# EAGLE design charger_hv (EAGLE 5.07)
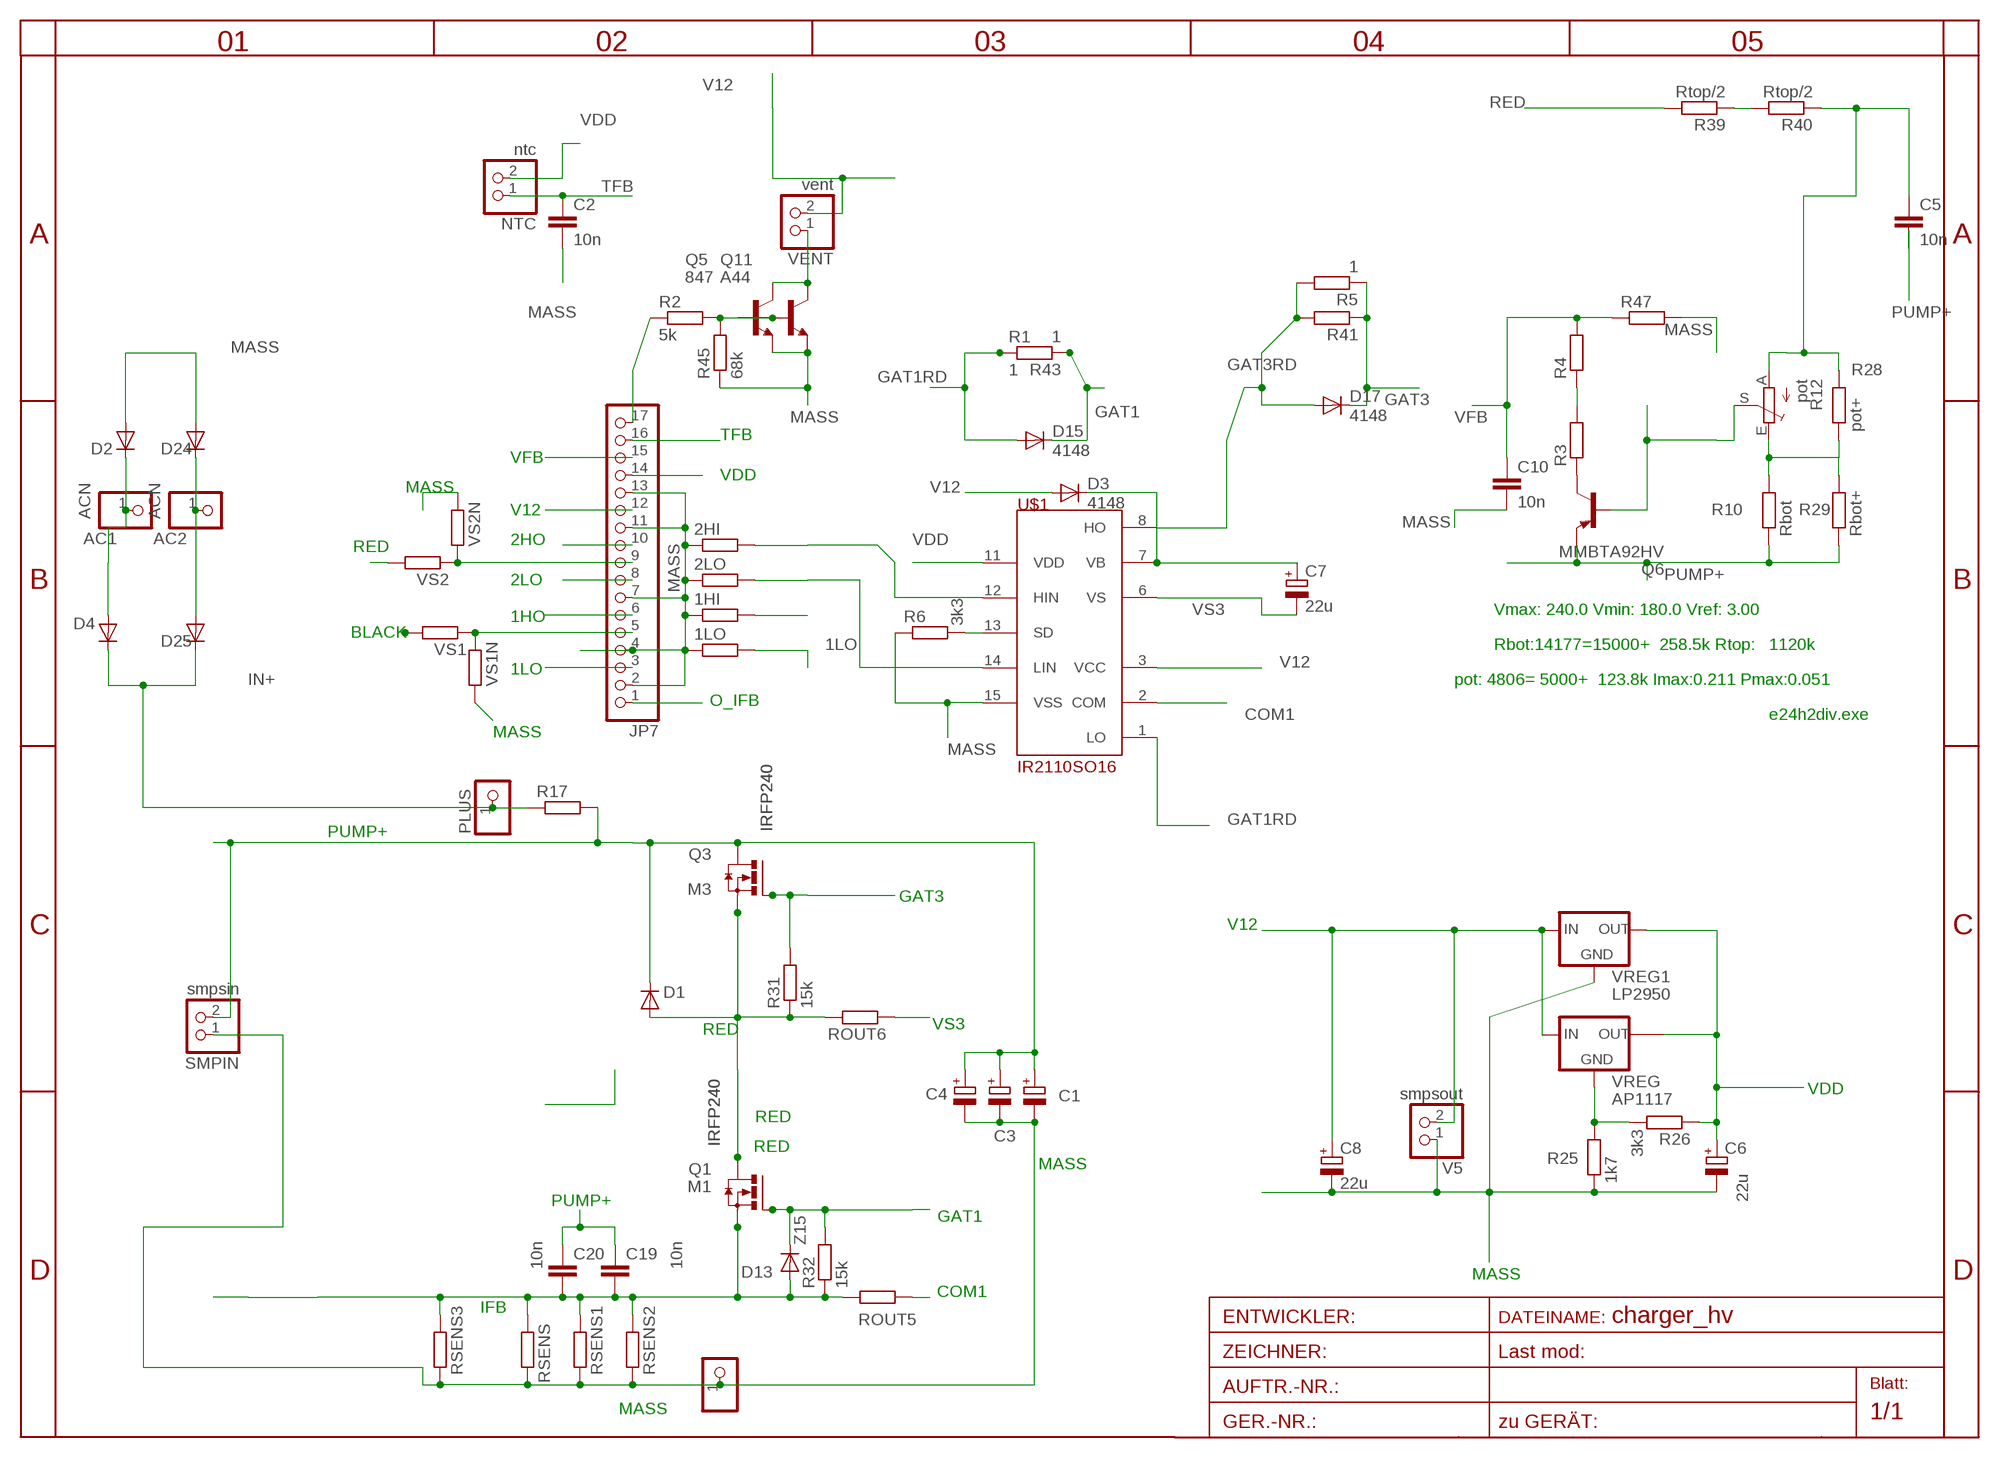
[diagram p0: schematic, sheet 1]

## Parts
1HI  R-EU_R0805  [R0805]
1LO  R-EU_R0805  [R0805]
2HI  R-EU_R0805  [R0805]
2LO  R-EU_R0805  [R0805]
AC1  ACN  PINHD-1X12MM3  [1X2MM3]
AC2  ACN  PINHD-1X12MM3  [1X2MM3]
C1  CPOL-EUE5-13  [E5-13]
C2  10n  C-EUC0805  [C0805]
C3  CPOL-EUE5-13  [E5-13]
C4  CPOL-EUE5-13  [E5-13]
C5  10n  C-EUC0805  [C0805]
C6  22u  CPOL-EUSMCA  [SMC_A]
C7  22u  CPOL-EUSMCA  [SMC_A]
C8  22u  CPOL-EUSMCA  [SMC_A]
C10  10n  C-EUC0805  [C0805]
C19  10n  C-EU050-024X044  [C050-024X044]
C20  10n  C-EU050-024X044  [C050-024X044]
D1  DIODE-TO220V  [TO220ACS]
D2  DIODE-TO220V  [TO220ACS]
D3  4148  DIODE-MINIMELF  [MINIMELF]
D4  DIODE-TO220V  [TO220ACS]
D13  Z15  DIODE-MINIMELF  [MINIMELF]
D15  4148  DIODE-MINIMELF  [MINIMELF]
D17  4148  DIODE-MINIMELF  [MINIMELF]
D24  DIODE-TO220V  [TO220ACS]
D25  DIODE-TO220V  [TO220ACS]
JP7  PINHD-1X17  [1X17]
M1  IRFP240  [TO247BV]
M3  IRFP240  [TO247BV]
MINUS  PINHD-1X12MM3  [1X2MM3]
NTC  ntc  PINHD-1X2STR  [1X02]
PLUS  PINHD-1X12MM3  [1X2MM3]
Q1  IRFP240  [TO247BV]
Q3  IRFP240  [TO247BV]
Q5  847  SMBTA45HV  [SOT23HV]
Q6  MMBTA92HV  [SOT23HV]
Q11  A44  -NPN-TO92-EBC  [TO92-EBC]
R1  1  R-EU_R2512  [R2512]
R2  5k  R-EU_R0603  [R0603]
R3  R-EU_R1206  [R1206]
R4  R-EU_R1206  [R1206]
R5  1  R-EU_R2512  [R2512]
R6  3k3  R-EU_R0805  [R0805]
R10  Rbot  R-EU_R0805  [R0805]
R12  pot  TRIM_EU-B64Y  [B64Y]
R17  R-EU_0309/10  [0309/10]
R25  1k7  R-EU_R0805  [R0805]
R26  3k3  R-EU_R0805  [R0805]
R28  pot+  R-EU_R0805  [R0805]
R29  Rbot+  R-EU_R0805  [R0805]
R31  15k  R-EU_R1206  [R1206]
R32  15k  R-EU_R1206  [R1206]
R39  Rtop/2  R-EU_R1206  [R1206]
R40  Rtop/2  R-EU_R1206  [R1206]
R41  1  R-EU_R1210  [R1210]
R43  1  R-EU_R1210  [R1210]
R45  68k  R-EU_R0805  [R0805]
R47  R-EU_R0805  [R0805]
ROUT5  R-EU_R2512  [R2512]
ROUT6  R-EU_R2512  [R2512]
RSENS  R-EU_WIRE  [WIRE]
RSENS1  R-EU_0309/10  [0309/10]
RSENS2  R-EU_0309/12  [0309/12]
RSENS3  R-EU_R2512  [R2512]
SMPIN  smpsin  PINHD-1X2STR  [1X02]
U$1  IR2110SO16  [SO16DW]
V5  smpsout  PINHD-1X2STR  [1X02]
VENT  vent  PINHD-1X2STR  [1X02]
VREG  AP1117  [SOT223]
VREG1  LP2950  LP2950TO92-2MIL  [TO92-2MIL]
VS1  R-EU_R1005  [R1005]
VS1N  R-EU_R0805  [R0805]
VS2  R-EU_R1005  [R1005]
VS2N  R-EU_R0805  [R0805]

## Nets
1HO: JP7.6
1LO: 1LO.2 JP7.3
2HO: 2HI.2 JP7.10 U$1.12(HIN)
2LO: 2LO.2 JP7.8 U$1.14(LIN)
BLACK: VS1.2
COM1: ROUT5.1 U$1.2(COM)
DFG: JP7.9 VS2.1 VS2N.2
GAT1: D13.C D15.C M1.G Q1.G R1.2 R32.2 R43.1
GAT1RD: D15.A R1.1 R43.2 U$1.1(LO)
GAT3: D17.C M3.G Q3.G R5.1 R31.2 R41.1
GAT3RD: D17.A R5.2 R41.2 U$1.8(HO)
GGG: AC1.1 D2.C D4.A
IFB: C19.2 C20.2 D13.A M1.S Q1.S R32.1 ROUT5.2 RSENS1.1 RSENS2.1 RSENS3.1 RSENS.1
IN+: D4.C D25.C PLUS.1 R17.1
JDH: JP7.5 VS1.1 VS1N.1
MASS: 1HI.1 1LO.1 2HI.1 2LO.1 C1.- C2.2 C3.- C4.- C6.- C8.- C10.2 D2.A D24.A JP7.2 JP7.4 JP7.7 JP7.11 JP7.13 MINUS.1 Q5.2(E) Q11.E R6.1 R25.1 R45.1 R47.2 RSENS1.2 RSENS2.2 RSENS3.2 RSENS.2 SMPIN.1 U$1.15(VSS) V5.1 VREG1.2(GND) VS1N.2 VS2N.1
N$1: Q5.3(C) Q11.C VENT.1
N$2: Q5.1(B) Q11.B R2.2 R45.2
N$3: JP7.17 R2.1
N$4: R6.2 U$1.13(SD)
N$5: Q6.3(C) R3.1
N$6: R3.2 R4.1
N$8: 1HI.2
N$15: R39.1 R40.2
N$17: R25.2 R26.2 VREG.1(GND)
N$19: C5.1 R12.A R28.2 R40.1
N$21: Q6.1(B) R12.S
N$22: AC2.1 D24.C D25.A
N$29: R10.2 R12.E R28.1 R29.2
O_IFB: JP7.1
PUMP+: C1.+ C3.+ C4.+ C5.2 C19.1 C20.1 D1.C M3.D Q3.D Q6.2(E) R10.1 R17.2 R29.1 SMPIN.2
RED: D1.A M1.D M3.S Q1.D Q3.S R31.1 R39.2 ROUT6.2 VS2.2
TFB: C2.1 JP7.16 NTC.1
V12: C8.+ D3.A JP7.12 U$1.3(VCC) V5.2 VENT.2 VREG1.3(IN) VREG.3(IN)
VB: C7.+ D3.C U$1.7(VB)
VDD: C6.+ JP7.14 NTC.2 R26.1 U$1.11(VDD) VREG1.1(OUT) VREG.4(TAB)
VFB: C10.1 JP7.15 R4.2 R47.1
VS3: C7.- ROUT6.1 U$1.6(VS)
Unconnected: VREG.2(OUT)

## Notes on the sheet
- Vmax: 240.0 Vmin: 180.0 Vref: 3.00
- Rbot:14177=15000+  258.5k Rtop:   1120k
- pot: 4806= 5000+  123.8k Imax:0.211 Pmax:0.051
- e24h2div.exe

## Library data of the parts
1HI 1LO 2HI 2LO R1-R5 R17 R31 R32 R45 R47 ROUT5 ROUT6 RSENS RSENS1-RSENS3 VS1 VS1N VS2 VS2N = rcl:R-EU_: RESISTOR, European symbol
AC1 AC2 MINUS PLUS = pinhead:PINHD-1X1: PIN HEADER
C1 C3 C4 C6-C8 = rcl:CPOL-EU: POLARIZED CAPACITOR, European symbol
C2 C5 C10 C19 C20 = rcl:C-EU: CAPACITOR, European symbol
D1-D4 D13 D15 D17 D24 D25 = diode:DIODE-: DIODE
JP7 = pinhead:PINHD-1X17: PIN HEADER
M1 M3 Q1 Q3 = transistor-power:IRFP240: HEXFET Power MosFet Source: http://www.irf.com/
NTC SMPIN V5 VENT = pinhead:PINHD-1X2: PIN HEADER
Q5 = transistor-npn:SMBTA45
Q6 = transistor-pnp:MMBTA92*: PNP Transistror
Q11 = transistor-neu-to92:*-NPN-: NPN Transistror
R6 R10 R25 R26 R28 R29 R39-R41 R43 = rcl-2:R-EU_: RESISTOR, European symbol
R12 = pot:TRIM_EU-: POTENTIOMETER
U$1 = ir2112:IR2110
VREG = v-reg:AP1117
VREG1 = v-reg:LP2950?*: Source: http://cache.national.com/ds/LP/LP2950.pdf

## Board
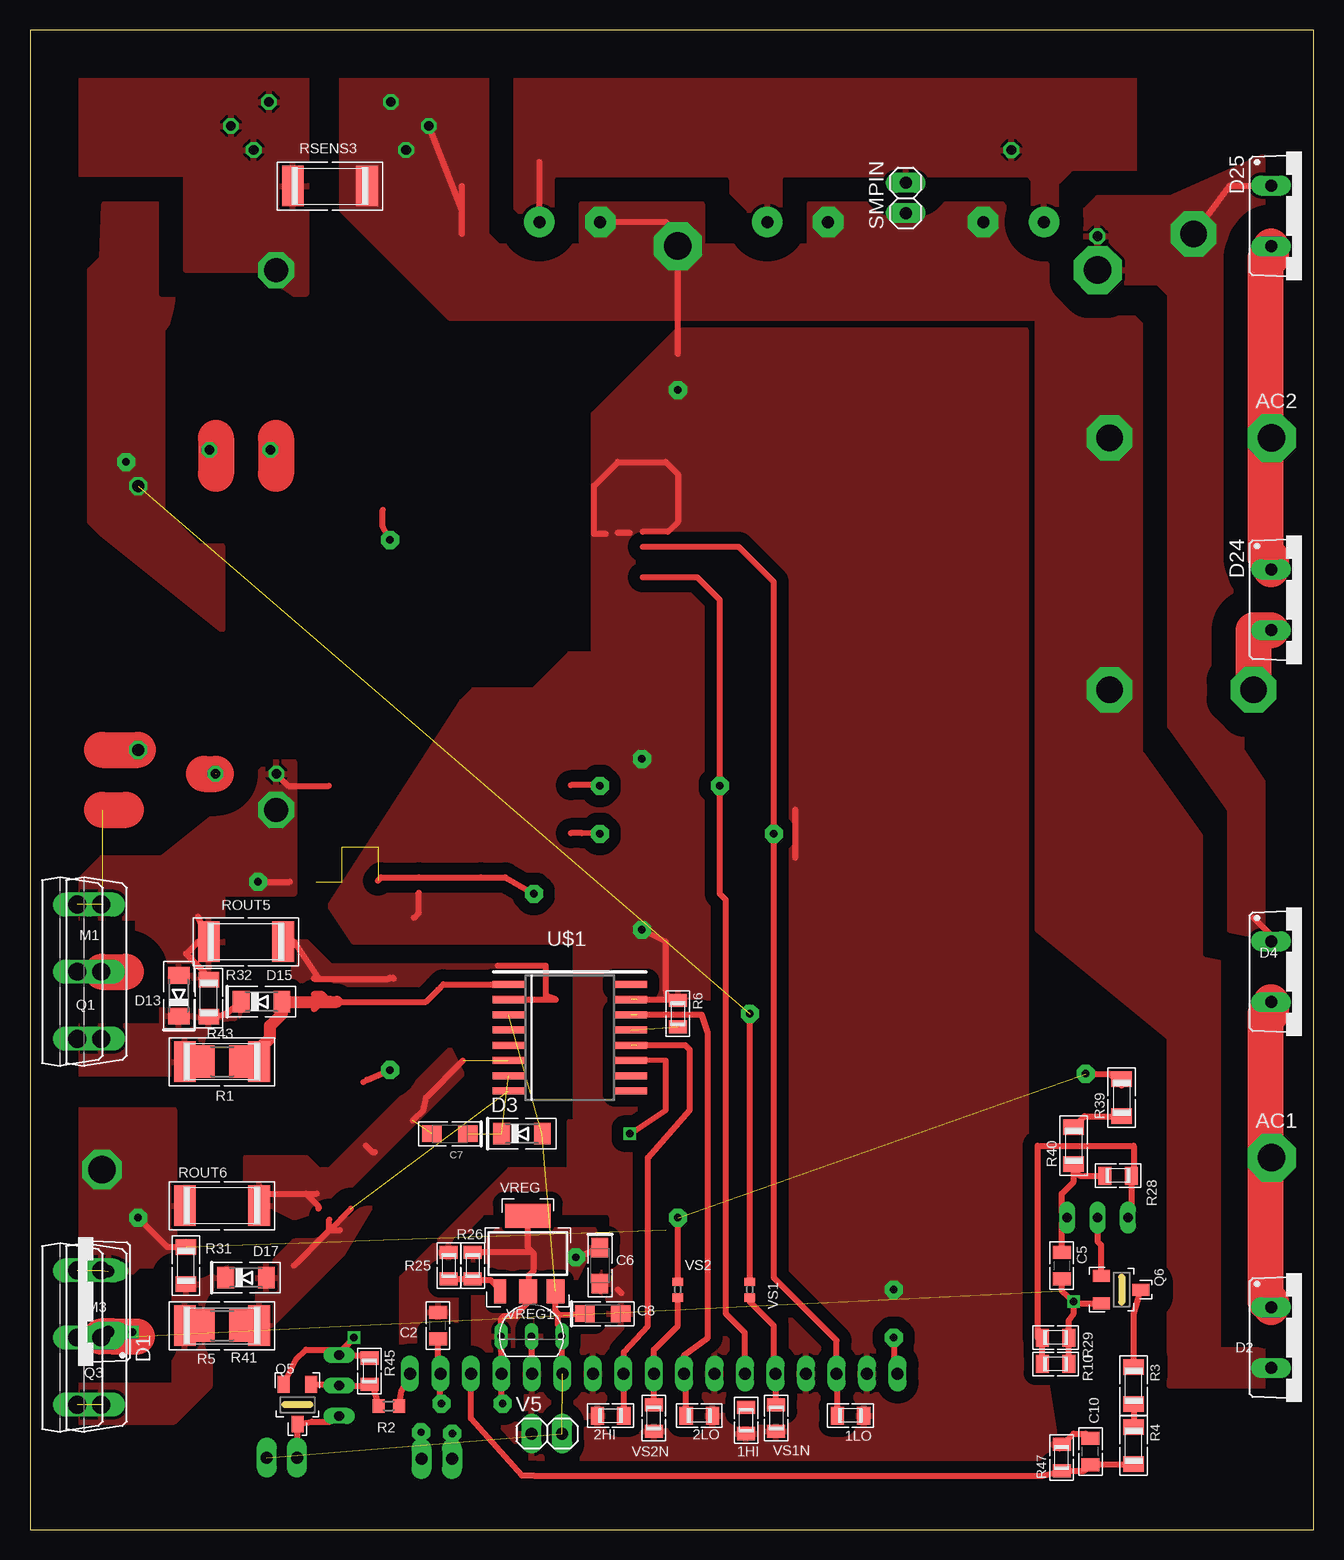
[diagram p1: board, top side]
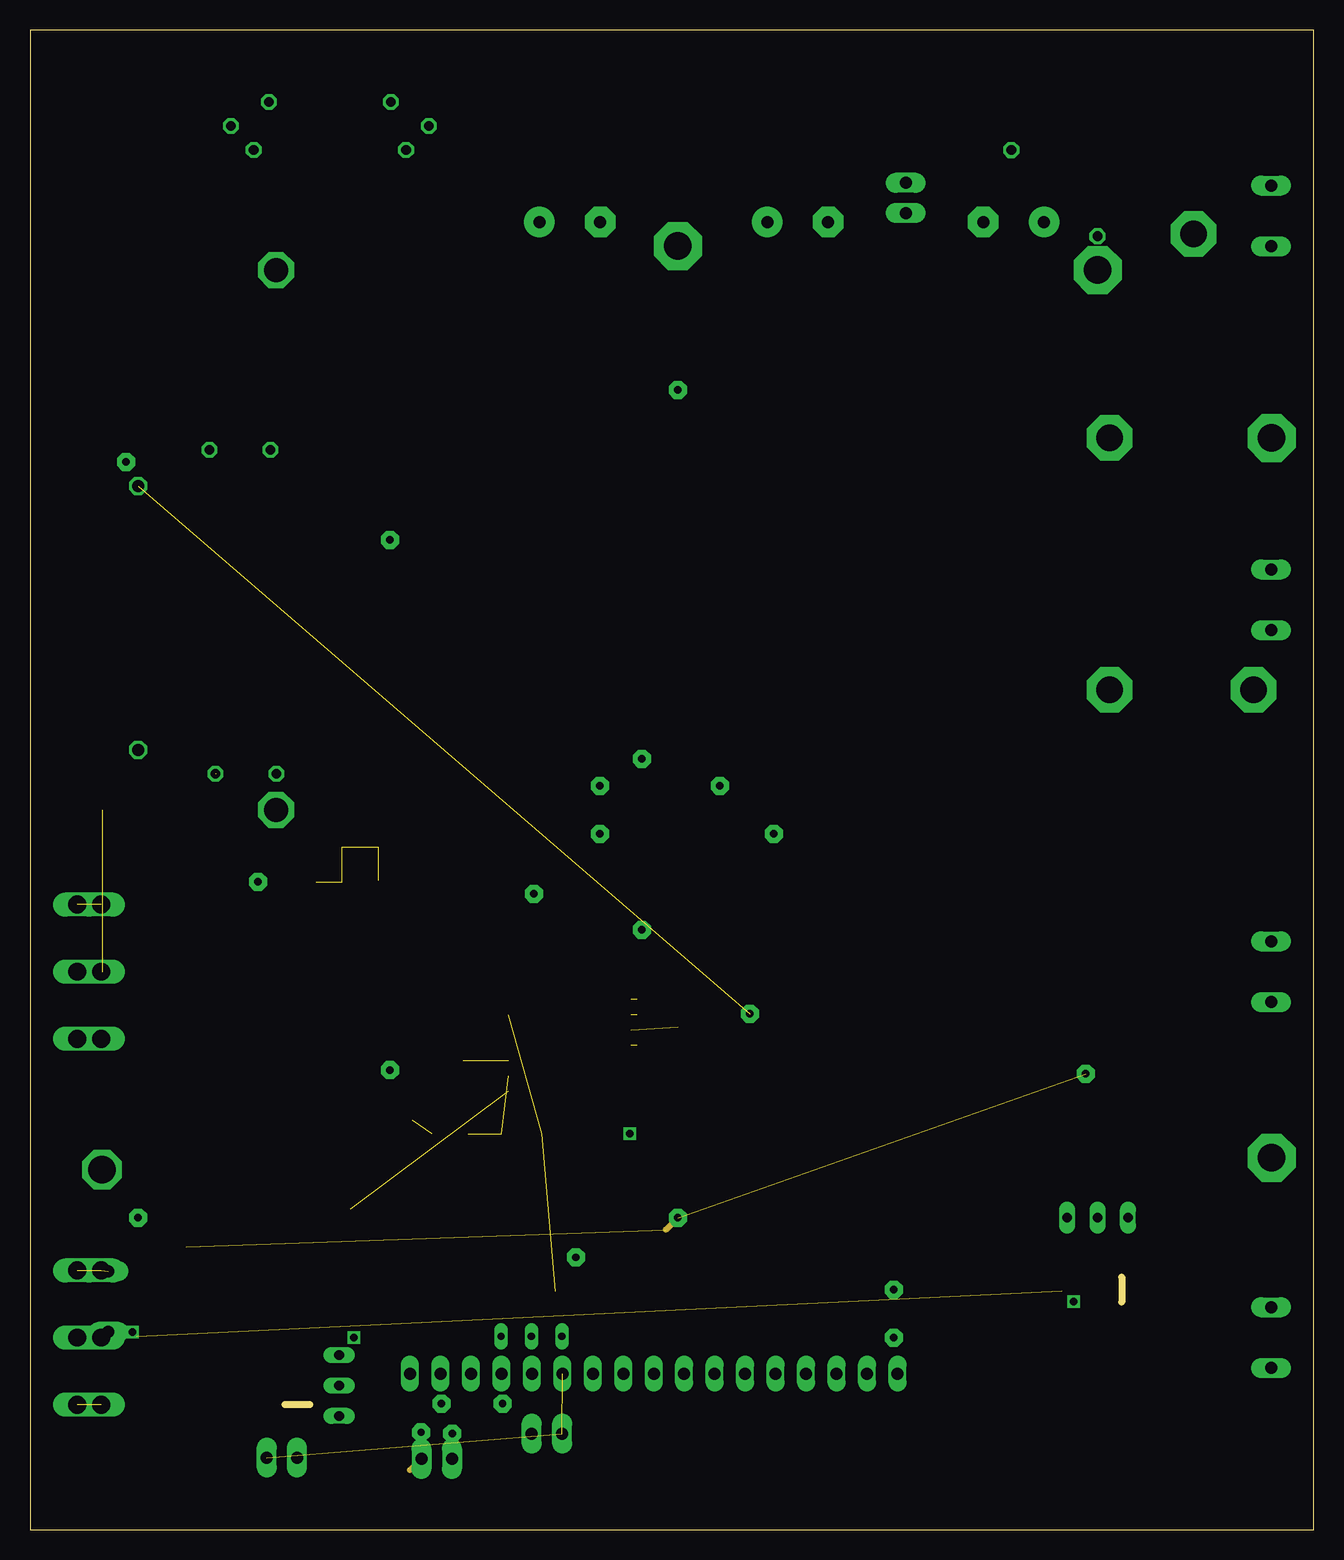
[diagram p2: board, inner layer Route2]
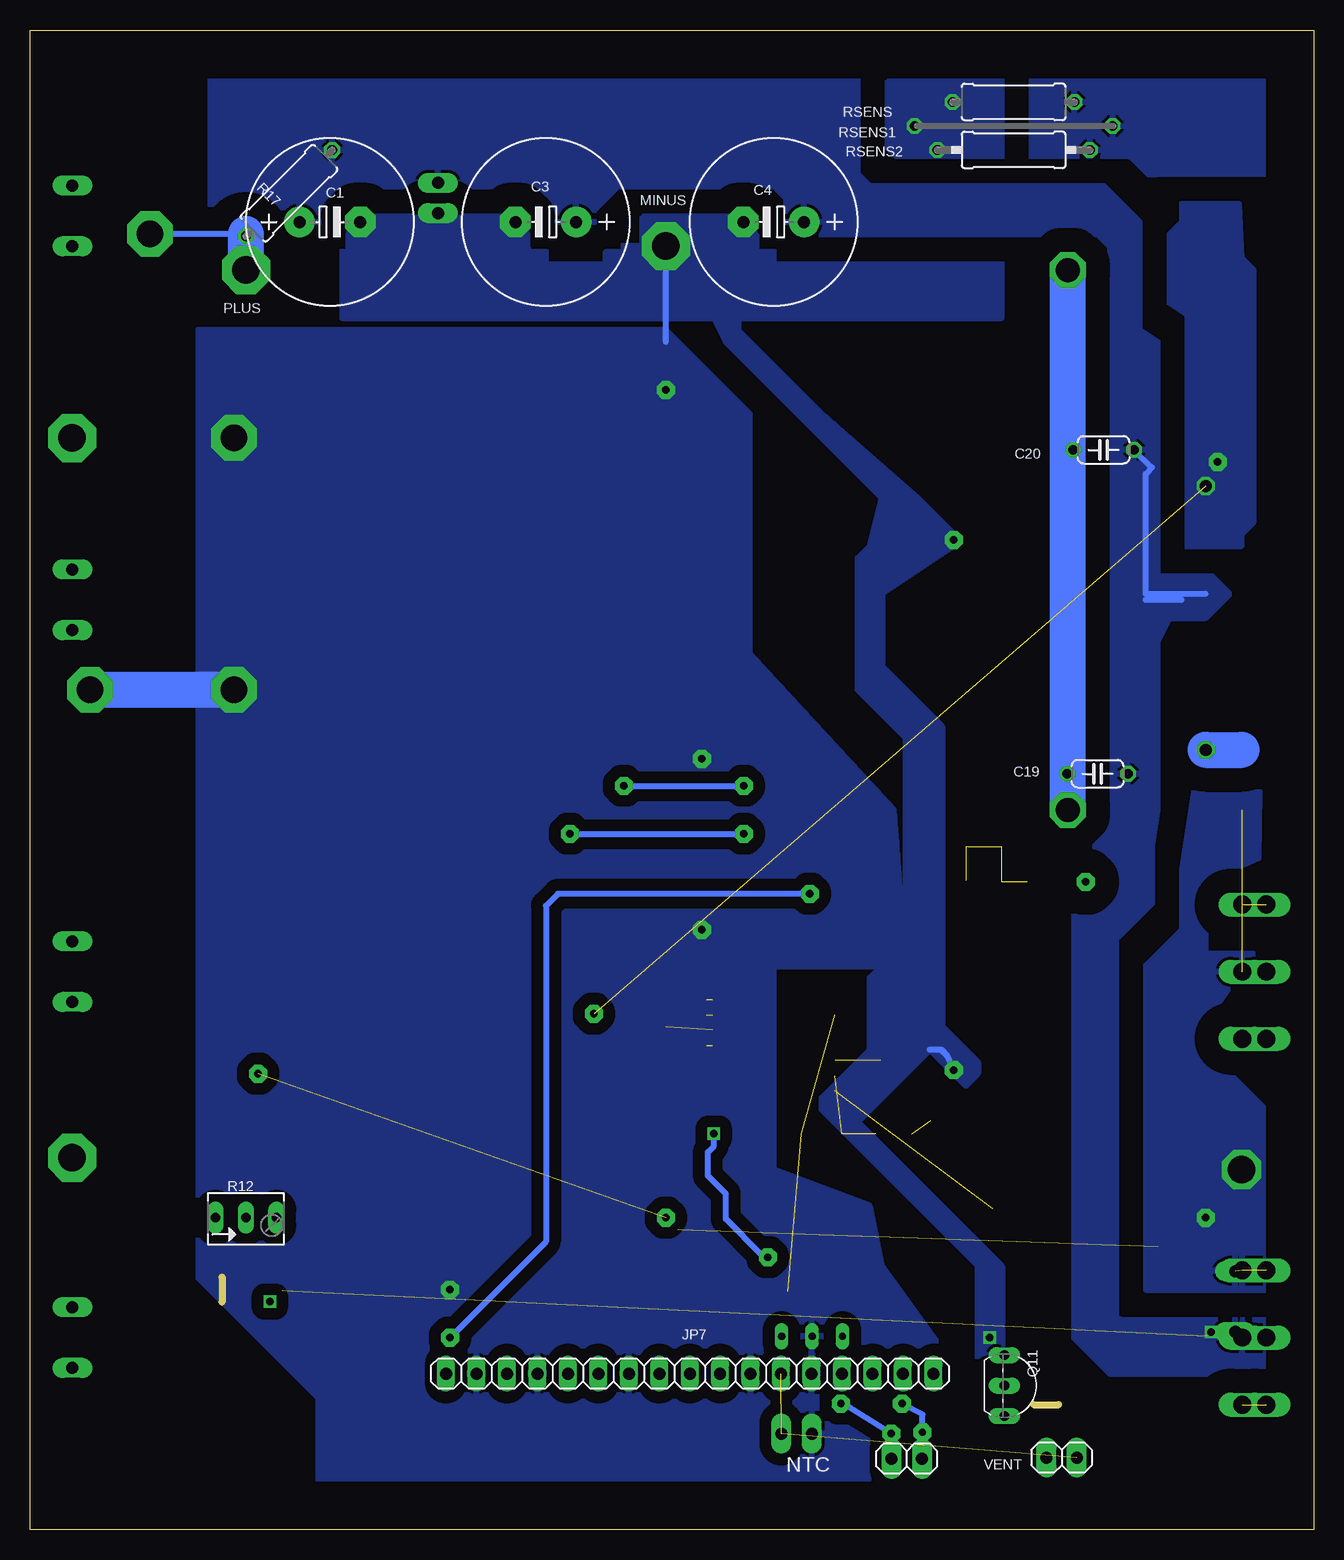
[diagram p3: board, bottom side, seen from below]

Size 107 x 125 mm. Coordinates in mm from the lower left corner, seen from the top.
Outline: 0,0 107,0 107,125 0,125 0,0
Copper layers (1*16): Top 0.035mm / dielectric 1.5mm / Bottom 0.035mm
Design rules "default *": minimum track width 10mil, minimum drill 20mil, track to track 8mil, track to pad 8mil, pad to pad 8mil, via to via 8mil, smd to smd 8mil, copper to edge 4mm, drill to drill 8mil, minimum pad ring 10mil, minimum via ring 8mil, stop-mask expansion 4mil, vias tented up to drill 0mil, thermal gap 10mil

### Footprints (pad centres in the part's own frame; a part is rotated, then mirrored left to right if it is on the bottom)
R0805 = smd 1.1 x 1.5: 1 -1.1,0; 2 1.1,0
1X2MM3 = drill 2.3 pad 4 octagon: 1 0,0
E5-13 = drill 1 pad 2.54 round: + -2.54,0 | drill 1 pad 2.54 octagon: - 2.54,0
C0805 = smd 1.1 x 1.5: 1 -1.1,0; 2 1.1,0
SMC_A = smd 1.6 x 1.4: + -1.5,0; - 1.5,0
C050-024X044 = drill 0.8 octagon: 1 -2.54,0; 2 2.54,0
TO220ACS = drill 1 pad 1.676 long: A 2.54,-2.54; C -2.54,-2.54
MINIMELF = smd 1.4 x 1.8: A 1.7,0; C -1.7,0
1X17 = drill 1 long: 1 -20.32,0; 2 -17.78,0; 3 -15.24,0; 4 -12.7,0; 5 -10.16,0; 6 -7.62,0; 7 -5.08,0; 8 -2.54,0; 9 0,0; 10 2.54,0; 11 5.08,0; 12 7.62,0; 13 10.16,0; 14 12.7,0; 15 15.24,0; 16 17.78,0; 17 20.32,0
TO247BV = drill 1.499 long: D 0,-2.921; G -5.588,-2.921; S 5.588,-2.921
1X02 = drill 1 pad 1.676 long: 1 -1.27,0; 2 1.27,0
SOT23HV = smd 1 x 1.4: 1 -1.15,-1.7; 2 1.15,-1.7; 3 0,1.6
TO92-EBC = drill 0.813 long: B 0,-1.27; C 2.54,-1.27; E -2.54,-1.27
R2512 = smd 1.8 x 3.4: 1 -3.1,0; 2 3.1,0
R0603 = smd 1 x 1.1: 1 -0.85,0; 2 0.85,0
R1206 = smd 1.3 x 1.7: 1 -1.55,0; 2 1.55,0
B64Y = drill 0.813 long: A 2.54,0; E -2.54,0; S 0,0
0309/10 = drill 0.813 octagon: 1 -5.08,0; 2 5.08,0
R1210 = smd 1.6 x 2.7: 1 -1.4,0; 2 1.4,0
WIRE = drill 0.813 octagon: 1 -8.25,0; 2 8.25,0
0309/12 = drill 0.813 octagon: 1 -6.35,0; 2 6.35,0
SO16DW = smd 0.6 x 2.7: 1 -4.445,-5.1; 2 -3.175,-5.1; 3 -1.905,-5.1; 4 -0.635,-5.1; 5 0.635,-5.1; 6 1.905,-5.1; 7 3.175,-5.1; 8 4.445,-5.1; 9 4.445,5.1; 10 3.175,5.1; 11 1.905,5.1; 12 0.635,5.1; 13 -0.635,5.1; 14 -1.905,5.1; 15 -3.175,5.1; 16 -4.445,5.1
SOT223 = smd 1 x 2: 1 -2.3,-3.15 | smd 1.5 x 2: 2 0,-3.15; 3 2.3,-3.15 | smd 3.8 x 2: 4 0,3.15
TO92-2MIL = drill 0.6 pad 0.813 long: 1 -2.54,0; 2 0,0; 3 2.54,0
R1005 = smd 0.7 x 0.9: 1 -0.65,0; 2 0.65,0

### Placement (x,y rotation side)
1HI  59.7,9.1 90 top
1LO  68.4,9.5 180 top
2HI  48.4,9.5 0 top
2LO  55.8,9.5 180 top
AC1  103.5,31 0 top
AC2  103.5,91 0 top
C1  82,109 0 bottom
C2  34,17 90 top
C3  64,109 180 bottom
C4  45,109 180 bottom
C5  86,22 270 top
C6  47.5,22 270 top
C7  35,33 180 top
C8  47.75,18 0 top
C10  88.4,6.5 90 top
C19  18,63 180 bottom
C20  17.5,90 180 bottom
D1  4,19 90 top
D2  106,16 270 top
D3  41,33 0 top
D4  106,46.5 270 top
D13  12.4,44.5 90 top
D15  19.3,44 0 top
D17  18,21 0 top
D24  106,77.5 270 top
D25  106,109.5 270 top
JP7  52,13 0 bottom
M1  3,46.5 90 top
M3  3,16 90 top
MINUS  54,107 270 bottom
NTC  33.9,5.9 180 bottom
PLUS  89,105 270 bottom
Q1  1,46.5 90 top
Q3  1,16 90 top
Q5  22.3,10.4 180 top
Q6  91,20 270 top
Q11  24.5,12 270 bottom
R1  16,39 180 top
R2  29.9,10.3 180 top
R3  92,12 270 top
R4  92,7 270 top
R5  16,17 0 top
R6  54,43 270 top
R10  85.5,13.8 180 top
R12  89,26 0 bottom
R17  85.4,111.4 45 bottom
R25  34.9,22 270 top
R26  36.9,22 270 top
R28  90.7,29.5 180 top
R29  85.5,16 180 top
R31  13,22 270 top
R32  14.9,44.3 270 top
R39  91,36 90 top
R40  87,32 90 top
R41  16,17 0 top
R43  16,39 0 top
R45  28.3,13.2 270 top
R47  86,6 90 top
ROUT5  18,49 180 top
ROUT6  16,27 180 top
RSENS  25,117 180 bottom
RSENS1  25,119 180 bottom
RSENS2  25,115 180 bottom
RSENS3  25,112 0 top
SMPIN  73,111 90 top
U$1  45,41 270 top
V5  43.1,8 0 top
VENT  21,6 0 bottom
VREG  41.5,23 0 top
VREG1  41.8,16.1 0 top
VS1  60,20 90 top
VS1N  62.2,9.3 270 top
VS2  54,20 90 top
VS2N  52,9.3 90 top

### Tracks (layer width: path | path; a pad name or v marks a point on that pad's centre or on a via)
1HO  (via drill 0.6 pad 1.5)
  Top 0.5: 45.1,62.05 46.95,62.05 v47.5,62 | 59.7,12.92 JP7.6 59.6,14.4 59.6,16.4 58,18 58,52.5 57.5,53 v57.5,62 57.5,73 57.5,77.5 56,79 55.63,79.36 51.1,79.36
  Bottom 0.5: v57.5,62 v47.5,62
1LO  (via drill 0.6 pad 1.5)
  Top 0.5: 45.1,58.05 46,58.05 v47.5,58 | 1LO.2 67.3,12.94 JP7.3 67.24,15.76 62,21 v62,58 62,79 59.09,81.91 51.1,81.91
  Bottom 0.5: v62,58 v47.5,58
2HO  (1 unrouted)
  Top 0.5: 2HI.2 49.5,12.96 JP7.10 49.5,14.8 51.5,17 51.5,21 51.5,22 51.5,31 55,35 55,40 54.63,40.37 50.6,40.37
2LO  (1 unrouted)
  Top 0.5: 2LO.2 54.7,12.84 JP7.8 54.54,14.54 56.5,16 56.5,41.41 56,42.91 50.6,42.91
BLACK  (via drill 0.6 pad 1.5, 1 pad 1.5)  (1 unrouted)
  Top 0.5: VS1.2 v60,43
  other vias: 9,87 8,89
  pour Bottom (isolate 2, rank 3): 6.2,110.5 11,110.5 11,109 13,107 13,101 11,99 11,82 6,82 6,83 5,84 5,105 6,106
  pour Top (isolate 2, rank 3): 6.2,110.5 10.8,110.5 arc-41 11.4,100.5 11,100 11,85 14,82 16,82 16,75 6,83 5,84 5,105 6,106
COM1
  Top 0.406: U$1.2 40.4,44.17
  Top 0.5: ROUT5.1 22,49 24,46 23.77,46 23.67,45.91 29.91,45.91 30,46 30.23,46 30.33,45.91 | 39,47 43,47 43,46 43,44.5 43.83,44.17 40.4,44.17
  pour Top (isolate 1): 22,49 23,49 25,47 39,47 39,45 37,45 23,45 22,46 22,48
DFG
  Top 0.5: VS2.1 54,17 52,15 JP7.9 VS2N.2
GAT1
  Top 0.5: R32.2 16.25,42.95 D15.C | Q1.G M1.G
  Top 1: R43.1 R1.2
  pour Top (isolate 2): 3,42 11,42 11,44 18,44 16,38 3,38
GAT1RD
  Top 0.5: 25,44 25.58,44 33,44 34,45 34.45,45.45 U$1.1 | 25,44 24.3,44 23.67,43.37 | 23.67,44.63 24.36,44.63 25,44
  Top 1: 25.58,44 25,44 D15.A 21,43 20,42 20,41 19.1,40.1 R1.1 R43.2
GAT3  (1 unrouted)
  pour Top (isolate 2, rank 3): 3,12 3,9 12,9 15,12 15,18 17,22 12,20 12,12
GAT3RD  (1 unrouted)
  Top 0.5: 22,22 24.95,24.95 | 24.95,24.95 24.95,25.84 | 24.95,24.95 25,25 | 25,25 26.74,26.74 | 25.84,24.95 25.05,24.95 25,25 | R41.2 R5.2
  pour Top (isolate 1.5, rank 3): 22,24 29,28 26,23 20,17 19,17 19,22 20,22
GGG
  Top 3: 103,31 AC1.1 103,31 | 103,31 103,43 103.46,43 D4.A | 103,31 103,26 103,19 103.46,19 D2.C
IFB  (via drill 0.6 pad 1.5, 2 pad 1.5)  (1 unrouted)
  Top 0.5: 14,51.1 ROUT5.2 14,49 13,48 14.5,46.5 R32.1 | 20.5,91 20.5,90.46 C20.2 | 24.9,62 21.54,62 C19.2 | v19,54 21.65,54
  Top 3: 20.5,91 20.5,88
  Bottom 0.5: v20.5,105 20.5,90.46 C20.2
  Bottom 3: v20.5,60 v20.5,105
  pour Top (isolate 2, rank 2): 3,51 3,54 4,54 6,56 11,56 16,60 20,64 22,64 22,53 16,53 16,46 9,46 9,51
  pour Top (isolate 2): 3,121 23,121 23,103 22,103 19,105 13,105 13,113 4,113 3,114
  pour Bottom (isolate 2, rank 4): 3,121 24,121 24,113 4,113 3,114
IN+  (via drill 2.2 pad 3.81)
  Top 0.5: D4.C 103.46,49.54 102,51 | D25.C 100.04,112.04 v97,108
  Bottom 0.5: v97,108 89.18,108 R17.1
  Bottom 3: PLUS.1 89,108
  pour Top (isolate 2): 104,115 95,111 89,111 88,110 88,104 94,104 95,103 95,67 100,60 100,50 105,49 105,59 101,65 101,108 104,109
JDH
  Top 0.5: VS1.1 60,19 62,17 62,13.16 JP7.5 62.2,12.96 VS1N.1
MASS  (via drill 0.6, 0.6 pad 1.5, 2.2 pad 3.81)  (1 unrouted)
  Top 0.5: 36,110 36,112 | 47,109 C4.- 53,109 54,108 54,98 | 36,108 36,110 | 36,110 RSENS.2 | 49,20 49.3,19.7 | 32.4,53.09 32.4,51.4 32,51 | 50.6,44.17 53.17,44.17 53,45 53,49 v51,50 | 29.4,85 29.4,83.6 v30,82.5 | 51.1,83.17 53.17,83.17 54,84 54,88 53,89 49,89 47,87 47,83 48,83 | 27.8,37.3 28.1,37.5 v30,38.3 | JP7.13 41.84,16.06 VREG1.2 | v27,16 26.73,15.73 | Q5.2 22.15,14.15 23,15 26,15 v27,16 | v27,16 26.77,15.77 Q11.E 28.06,14.54 R45.1 | 63.8,56 63.8,60 | 49,83.1 50,83.1 | R47.2 86.1,7.1 87,8 88,8 C10.2
  Top 3: D24.A 102,74.96 v102,70
  Bottom 0.5: v30,38.3 30.57,39.5 | 30.57,39.5 31,40 | 54,99 MINUS.1 | 32,40 31.06,40 30.57,39.5
  Bottom 3: v90,70 v102,70
  other vias: 51,64.25 54,95 72,20 90,91
  pour Bottom (isolate 1, rank 4): 35,60 47,73 47,93 54,100 93,100 93,21 83,11 83,4 23,4 36,22 37,27 45,30 45,47 34,47
  pour Top (isolate 1, rank 4): 47,93 54,100 83,100 83,23 86,4 31,4 31,21 40,30 45,30 45,34 45.5,34 45.5,49 27,49 25,52 36,69 37,70 42,70 45,73 47,73
  pour Bottom (isolate 2, rank 3, no thermals): 26,101 26,121 35,121 38,119 38,108 39,107 45.8,107 48,110 56,110 56,107 65,107 65,110 80,110 81,109 81,101
  pour Top (isolate 2, rank 2, no thermals): 26,121 38,121 38,108 39,107 46,107 46,110.5 56,110.5 56,107 65,107 65,110.5 81,110.5 88,101 92,101 93,100 93,67 99,55 99,15 105,15 106,14 106,13 105,12 95,12 95,41 84,50 84,101 35,101 26,110
  pour Bottom (isolate 2): 26,22 26,14 28,14 28,22 41,35 41,36 37,40 37,46 34,49 34,66 38,70 38,81 37,82 36,86 49,99 50,101 48,103 48,100 41,93 33,86 30,83 30,82 36,78 36,72 31,67 31,42 28,39 28,38 29,37 32,40 38,34
N$1
  Top 0.5: VENT.1 22.3,7.03 Q5.3 23.5,9 25,9 25.46,9.46 Q11.C
N$2
  Top 0.5: Q5.1 26.67,12.1 Q11.B 28.55,12 | 28.55,12 R2.2 | 28.55,12 28.4,12 R45.2
N$3
  Top 0.5: R2.1 30.98,11.6 JP7.17
N$4  (1 unrouted)
N$5
  Top 0.5: R3.1 92,16 92,18 Q6.3
N$6
  Top 0.5: R4.1 92.1,8.55 R3.2
N$13  (via drill 1 pad 1.5)
  Top 3: 6,65 v9,65
  Bottom 3: v9,65 6,65
N$15
  Top 0.5: R39.1 87.9,34.45 R40.2
N$17
  Top 0.5: R25.2 R26.2 37.1,20.8 38.4,20.8 39.2,20 VREG.1
N$19
  Top 0.5: 87,29 87,30 | 87,30 R40.1 | 87,29 86,28 86,26.46 R12.A 86,25.54 C5.1 | R28.2 87.5,29.5 87,30 | 87,29 87,30
N$21
  Top 0.5: Q6.1 89.3,23.7 89,24 R12.S
N$22
  Top 3: 103,91 AC2.1 | 103,91 103,94 103,106 103.46,106 D25.A | 103,91 103,81 103.46,81 D24.C
N$29
  Top 0.5: R10.2 R29.2 84,16 84,32 92,32 92,29.7 R28.1 91.8,26.26 R12.E
O_IFB  (via drill 0.6 pad 1.5)  (5 unrouted)
  Top 0.5: 29,54.1 29.27,54.37 32.4,54.37 37.6,54.37 39.63,54.37 v42,53 | v72,16 72,13.32 JP7.1
  Bottom 0.5: v42,53 63,53 64,52 64,24 v72,16
PUMP+  (via drill 0.6)  (2 unrouted)
  Top 0.5: C20.1 14.96,90.46 15.5,91 | C4.+ 42.46,114 | 6,16 6.9,16 7,16.1 | 6,16 M3.D | C5.2 86,19.9 v87,19 | R10.1 R29.1 86.6,17.4 87,18 v87,19 | Q6.2 87,18.85 v87,19 | v8.54,16.46 D1.C | v8.54,16.46 8.9,16.1 | v8.54,16.46 6.46,16.46 6,16 | Q3.D 6,16
  Top 3: 15.5,91 15.5,88 | 14.5,63 15.5,63 | 5.9,16.1 7,16.1 8.9,16.1
  Bottom 0.5: 14,78 14,88 13.46,88.54 C20.1 | 9,78 14,78 | 14,77.5 11,77.5 14,78 | v8.54,16.46 7.46,16.46 7,16
  pour Bottom (isolate 2, rank 2): 38,121 92,121 92,108 83,108 79,112 66,112 63,109 63,108 60,108 60,110 58,112 45,112 44,111 44,108 18,108 17,107 17,84 13,84 13,99 14.5,100 14.5,109 17.5,112 37,112 38,113
  pour Top (isolate 2, rank 4): 40,121 92,121 92,108 83,108 79,112 66,112 63,109 63,108 60,108 60,110 58,112 45,112 44,111 44,108 17,108 16,107 11,109 14,112 37,112 38,113
  pour Bottom (isolate 2, rank 4): 3,18 13,18 13,74 12,76 9,76 7,78 9,80 12,80 13,81 13,90 14,91 15,91 18,88 20,52 20,16 17,13 4,13 3,14
RED  (via drill 0.6 pad 1.5, 2.3 pad 1.5)  (5 unrouted)
  Top 0.5: VS2.2 v54,26 | R31.1 11.45,23.55 v9,26 | Q1.D M1.D 6,46.5 | v88,38 90,38 91,37 R39.2
  Top 3: 6,46.5 8,46.5 | 6,60 8,60
  Route2 0.5: v54,26 53,25
  other vias: 6,30
  pour Top (isolate 2): 4,21 4,35 12,35 12,24 13,24 11,22 9,22 8,21
  pour Bottom (isolate 2): 4.5,61.5 10,61.5 11,55 11,50 14,47 14,20 4,20 4,35 10,41 5,48 9,48 9,54 4.55,56
TFB  (via drill 0.6 pad 1.5)
  Top 0.5: C2.1 34,13.22 JP7.16 34.2,10.78 v34.3,10.5 | NTC.1 32.63,7.63 v32.6,8.1
  Route2 0.5: 31.68,4.95 NTC.1
  Bottom 0.5: v32.6,8.1 32.6,9.6 v34.3,10.5
V12  (4 unrouted)
  Top 0.5: 44.2,13.18 JP7.12 44.34,13.04 VREG1.3 44.3,16.14 44.3,16.8 44,17.1 44,18 | VREG.3 43.8,18.2 44,18 | C8.+ 44.1,17.9 44,18
VB  (2 unrouted)
VDD  (via drill 0.6, 0.6 pad 1.5)
  Top 0.406: 53,39.09 U$1.11 | C6.+ 48,24
  Top 0.5: 41.9,23.1 R26.1 | 41.9,23.1 42,23 42,21.6 41.6,21.2 41.6,19 40.4,17.8 39.5,17.8 39.26,17.56 VREG1.1 39.3,16.06 JP7.14 39.3,11.3 v39.4,10.5 | VREG.4 41.5,23.5 41.9,23.1 | v35.2,8 35,6.07 NTC.2 | v45.5,22.7 C6.+ | 53,39.09 53,35 v50,33
  Bottom 0.5: v39.4,10.5 39.4,10.6 v35.2,8 | v45.5,22.7 45.71,22.91 46.03,22.91 49,25.88 49,28 50.5,29.5 50.5,31.45 50,31.95 v50,33
  pour Top (isolate 0.8): 39,25 47,25 47,24 45,20 43,20 43,19 40,15 37,15 37,23
VFB
  Top 0.5: JP7.15 36.76,9.84 36.76,9.24 41,4.5 42,4.5 84.4,4.5 R47.1 87.9,4.9 C10.1 88.45,5.45 R4.2
VS3  (2 unrouted)
  Top 0.5: ROUT6.1 19.25,28.1 | 19.25,28.1 19.3,28.51 | 28.76,31.45 28.55,31.45 28,32 | 36.09,39.09 33,36 32.81,35 31.9,34.1 | 24.05,26.74 24.05,26.95 23,28 | 23,28 23.9,28 | 23,28 19.35,28 19.25,28.1
  pour Top (isolate 1.5, rank 2): 18,31 23,31 24,30 25,30 35,40 36,38 25,27 22,26 18,28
